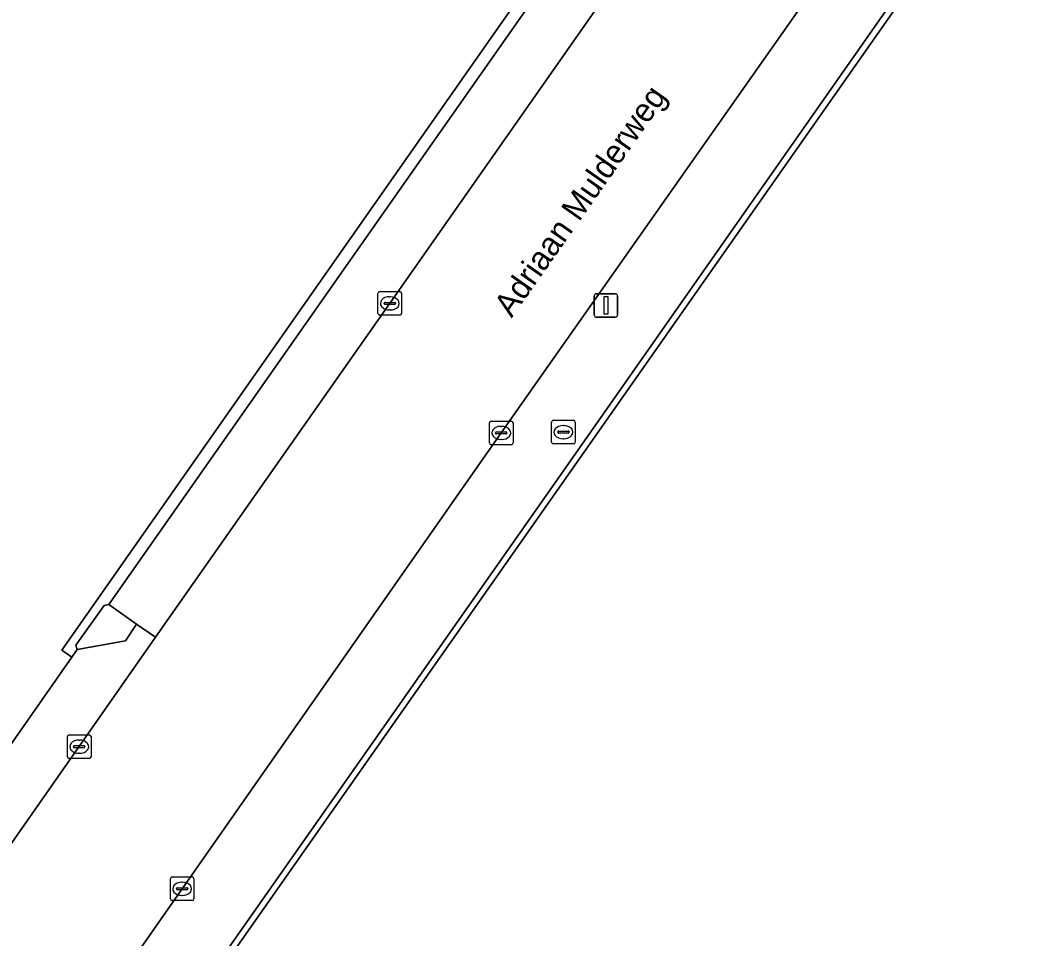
# Model space of a CAD drawing. Extents: x 155018 to 156648, y 383979 to 385733.
# Drawn here: x 155613.96 to 155656.36, y 384791.48 to 384830.45 of the extents above; entities that cross this region are included whole.
import ezdxf

# ---------------------------------------------------------------- set-up
doc = ezdxf.new("R2010")
doc.units = 0
for name, color, linetype in [('IMGEO_Brandkraan', 7, 'Continuous'), ('IMGEO_Erf', 7, 'Continuous'), ('IMGEO_Groenvoorziening', 7, 'Continuous'), ('IMGEO_Hek', 7, 'Continuous'), ('IMGEO_Kolk', 7, 'Continuous'), ('IMGEO_Lichtmast', 7, 'Continuous'), ('IMGEO_Openbare_ruimte_label', 7, 'Continuous'), ('IMGEO_Parkeervlak_open', 7, 'Continuous'), ('IMGEO_Rijbaan_lokaal_gesloten', 7, 'Continuous'), ('IMGEO_Verkeerseiland_open', 7, 'Continuous'), ('IMGEO_Voetpad_open', 7, 'Continuous')]:
    doc.layers.add(name, color=color, linetype=linetype)

msp = doc.modelspace()

# ---------------------------------------------------------------- linework, layer by layer
at = {"layer": 'IMGEO_Brandkraan'}
for p, q in [((155636.527, 384812.529), (155636.527, 384813.381)), ((155636.602, 384813.455), (155637.454, 384813.455)), ((155637.015, 384813.235), (155637.04, 384813.235)), ((155637.528, 384813.381), (155637.528, 384812.529)), ((155636.786, 384812.949), (155636.786, 384812.961)), ((155637.224, 384812.912), (155636.826, 384812.912)), ((155636.829, 384812.998), (155637.227, 384812.998)), ((155637.27, 384812.961), (155637.27, 384812.949)), ((155637.454, 384812.455), (155636.602, 384812.455)), ((155637.038, 384812.675), (155637.013, 384812.675))]:
    msp.add_line(p, q, dxfattribs=at)
for points in [[(155636.527, 384812.529), (155636.527, 384813.381)], [(155636.602, 384813.455), (155637.454, 384813.455)], [(155637.528, 384813.381), (155637.528, 384812.529)], [(155637.454, 384812.455), (155636.602, 384812.455)]]:
    msp.add_lwpolyline(points, dxfattribs=at)
for centre, radius, start, end in [((155636.604, 384813.379), 0.0765, 91.552, 178.448), ((155636.604, 384813.379), 0.0765, 91.552, 178.448), ((155637.452, 384813.379), 0.0765, 1.552, 88.448), ((155637.452, 384813.379), 0.0765, 1.552, 88.448), ((155636.826, 384812.958), 0.0403, 85.8775, 175.7526), ((155636.823, 384812.948), 0.0366, 178.938, 274.7102), ((155637.227, 384812.955), 0.043, 264.8664, 352.4533), ((155637.231, 384812.96), 0.0386, 1.7309, 96.639), ((155636.604, 384812.531), 0.0765, 181.552, 268.448), ((155636.604, 384812.531), 0.0765, 181.552, 268.448), ((155637.452, 384812.531), 0.0765, 271.552, 358.448), ((155637.452, 384812.531), 0.0765, 271.552, 358.448)]:
    msp.add_arc(centre, radius, start, end, dxfattribs=at)
for centre, major_axis, ratio, start_param, end_param in [((155637.014, 384812.955), (-0.387, 0.002), 0.722429, 4.712389, 7.853982), ((155637.039, 384812.955), (-0.39, 0.002), 0.717154, 1.570796, 4.712389)]:
    msp.add_ellipse(centre, major_axis=major_axis, ratio=ratio, start_param=start_param, end_param=end_param, dxfattribs=at)
at = {"layer": 'IMGEO_Erf'}
for points in [[(155730.975, 385018.536), (155724.402, 385000), (155719.139, 384985.171), (155718.598, 384983.687), (155716.009, 384976.585), (155715.7, 384975.738), (155702.844, 384939.771), (155702.172, 384937.868), (155696.786, 384922.628), (155696.12, 384920.743), (155684.958, 384889.381), (155684.425, 384889.57), (155682.806, 384885.06), (155682.424, 384883.902), (155681.972, 384882.563), (155681.138, 384880.234), (155681.15, 384879.519), (155676.547, 384866.454), (155676.35, 384866.575), (155669.497, 384856.797), (155669.212, 384856.331), (155667.198, 384853.508), (155667.02, 384853.625), (155588.106, 384741.158)], [(155553.633, 384715.232), (155553.739, 384715.172), (155553.747, 384715.183), (155566.056, 384732.66), (155578.198, 384750), (155612.129, 384798.458), (155612.508, 384798.198), (155616.168, 384803.406), (155615.737, 384803.696), (155649.459, 384851.832), (155649.247, 384851.98)]]:
    msp.add_lwpolyline(points, dxfattribs=at)
at = {"layer": 'IMGEO_Groenvoorziening'}
msp.add_lwpolyline([(155667.02, 384853.625), (155667.198, 384853.508), (155669.212, 384856.331), (155669.497, 384856.797), (155668.817, 384856.954), (155660.389, 384844.659), (155636.862, 384811.074), (155608.808, 384771.107), (155594.019, 384750), (155586.655, 384739.49), (155582.342, 384733.152), (155582.316, 384732.95), (155582.416, 384732.885), (155582.631, 384733.19), (155586.789, 384739.087), (155588.217, 384741.112), (155588.106, 384741.158)], close=True, dxfattribs=at)
at = {"layer": 'IMGEO_Hek'}
msp.add_lwpolyline([(155586.789, 384739.087), (155588.217, 384741.112), (155588.106, 384741.158), (155667.02, 384853.625), (155667.198, 384853.508), (155669.212, 384856.331)], dxfattribs=at)
at = {"layer": 'IMGEO_Kolk'}
for p, q in [((155629.158, 384817.995), (155629.158, 384818.847)), ((155629.233, 384818.921), (155630.085, 384818.921)), ((155629.646, 384818.701), (155629.671, 384818.701)), ((155630.159, 384818.847), (155630.159, 384817.995)), ((155629.417, 384818.415), (155629.417, 384818.427)), ((155629.855, 384818.378), (155629.457, 384818.378)), ((155629.46, 384818.464), (155629.858, 384818.464)), ((155629.901, 384818.427), (155629.901, 384818.415)), ((155630.085, 384817.921), (155629.233, 384817.921)), ((155629.669, 384818.141), (155629.644, 384818.141)), ((155633.888, 384812.493), (155633.888, 384813.345)), ((155633.963, 384813.419), (155634.815, 384813.419)), ((155634.376, 384813.199), (155634.401, 384813.199)), ((155634.889, 384813.345), (155634.889, 384812.493)), ((155634.147, 384812.913), (155634.147, 384812.925)), ((155634.585, 384812.876), (155634.187, 384812.876)), ((155634.19, 384812.962), (155634.588, 384812.962)), ((155634.631, 384812.925), (155634.631, 384812.913)), ((155634.815, 384812.419), (155633.963, 384812.419)), ((155634.399, 384812.639), (155634.374, 384812.639)), ((155615.977, 384799.176), (155615.977, 384800.028)), ((155616.052, 384800.102), (155616.904, 384800.102)), ((155616.978, 384800.028), (155616.978, 384799.176)), ((155616.236, 384799.596), (155616.236, 384799.608)), ((155616.279, 384799.645), (155616.677, 384799.645)), ((155616.465, 384799.882), (155616.49, 384799.882)), ((155616.72, 384799.608), (155616.72, 384799.596)), ((155616.674, 384799.559), (155616.276, 384799.559)), ((155616.488, 384799.322), (155616.463, 384799.322)), ((155616.904, 384799.102), (155616.052, 384799.102)), ((155620.42, 384794.069), (155621.272, 384794.069)), ((155620.345, 384793.143), (155620.345, 384793.995)), ((155620.833, 384793.849), (155620.858, 384793.849)), ((155621.346, 384793.995), (155621.346, 384793.143)), ((155620.604, 384793.563), (155620.604, 384793.575)), ((155621.042, 384793.526), (155620.644, 384793.526)), ((155620.647, 384793.612), (155621.045, 384793.612)), ((155620.856, 384793.289), (155620.831, 384793.289)), ((155621.088, 384793.575), (155621.088, 384793.563)), ((155621.272, 384793.069), (155620.42, 384793.069))]:
    msp.add_line(p, q, dxfattribs=at)
for points in [[(155629.158, 384817.995), (155629.158, 384818.847)], [(155629.233, 384818.921), (155630.085, 384818.921)], [(155630.159, 384818.847), (155630.159, 384817.995)], [(155630.085, 384817.921), (155629.233, 384817.921)], [(155633.888, 384812.493), (155633.888, 384813.345)], [(155633.963, 384813.419), (155634.815, 384813.419)], [(155634.889, 384813.345), (155634.889, 384812.493)], [(155634.815, 384812.419), (155633.963, 384812.419)], [(155615.977, 384799.176), (155615.977, 384800.028)], [(155616.052, 384800.102), (155616.904, 384800.102)], [(155616.978, 384800.028), (155616.978, 384799.176)], [(155616.904, 384799.102), (155616.052, 384799.102)], [(155620.42, 384794.069), (155621.272, 384794.069)], [(155620.345, 384793.143), (155620.345, 384793.995)], [(155621.346, 384793.995), (155621.346, 384793.143)], [(155621.272, 384793.069), (155620.42, 384793.069)]]:
    msp.add_lwpolyline(points, dxfattribs=at)
for centre, radius, start, end in [((155629.235, 384818.845), 0.0765, 91.552, 178.448), ((155629.235, 384818.845), 0.0765, 91.552, 178.448), ((155630.083, 384818.845), 0.0765, 1.552, 88.448), ((155630.083, 384818.845), 0.0765, 1.552, 88.448), ((155629.457, 384818.424), 0.0403, 85.8775, 175.7526), ((155629.454, 384818.414), 0.0366, 178.938, 274.7102), ((155629.858, 384818.421), 0.043, 264.8664, 352.4533), ((155629.862, 384818.426), 0.0386, 1.7309, 96.639), ((155629.235, 384817.997), 0.0765, 181.552, 268.448), ((155629.235, 384817.997), 0.0765, 181.552, 268.448), ((155630.083, 384817.997), 0.0765, 271.552, 358.448), ((155630.083, 384817.997), 0.0765, 271.552, 358.448), ((155633.965, 384813.343), 0.0765, 91.552, 178.448), ((155633.965, 384813.343), 0.0765, 91.552, 178.448), ((155634.813, 384813.343), 0.0765, 1.552, 88.448), ((155634.813, 384813.343), 0.0765, 1.552, 88.448), ((155634.187, 384812.922), 0.0403, 85.8775, 175.7526), ((155634.184, 384812.912), 0.0366, 178.938, 274.7102), ((155634.588, 384812.919), 0.043, 264.8664, 352.4533), ((155634.592, 384812.924), 0.0386, 1.7309, 96.639), ((155633.965, 384812.495), 0.0765, 181.552, 268.448), ((155633.965, 384812.495), 0.0765, 181.552, 268.448), ((155634.813, 384812.495), 0.0765, 271.552, 358.448), ((155634.813, 384812.495), 0.0765, 271.552, 358.448), ((155616.054, 384800.026), 0.0765, 91.552, 178.448), ((155616.054, 384800.026), 0.0765, 91.552, 178.448), ((155616.902, 384800.026), 0.0765, 1.552, 88.448), ((155616.902, 384800.026), 0.0765, 1.552, 88.448), ((155616.276, 384799.605), 0.0403, 85.8775, 175.7526), ((155616.273, 384799.595), 0.0366, 178.938, 274.7102), ((155616.677, 384799.602), 0.043, 264.8664, 352.4533), ((155616.681, 384799.607), 0.0386, 1.7309, 96.639), ((155616.054, 384799.178), 0.0765, 181.552, 268.448), ((155616.054, 384799.178), 0.0765, 181.552, 268.448), ((155616.902, 384799.178), 0.0765, 271.552, 358.448), ((155616.902, 384799.178), 0.0765, 271.552, 358.448), ((155620.422, 384793.993), 0.0765, 91.552, 178.448), ((155620.422, 384793.993), 0.0765, 91.552, 178.448), ((155621.27, 384793.993), 0.0765, 1.552, 88.448), ((155621.27, 384793.993), 0.0765, 1.552, 88.448), ((155620.644, 384793.572), 0.0403, 85.8775, 175.7526), ((155620.641, 384793.562), 0.0366, 178.938, 274.7102), ((155621.045, 384793.569), 0.043, 264.8664, 352.4533), ((155621.049, 384793.574), 0.0386, 1.7309, 96.639), ((155620.422, 384793.145), 0.0765, 181.552, 268.448), ((155620.422, 384793.145), 0.0765, 181.552, 268.448), ((155621.27, 384793.145), 0.0765, 271.552, 358.448), ((155621.27, 384793.145), 0.0765, 271.552, 358.448)]:
    msp.add_arc(centre, radius, start, end, dxfattribs=at)
for centre, major_axis, ratio, start_param, end_param in [((155629.645, 384818.421), (-0.387, 0.002), 0.722429, 4.712389, 7.853982), ((155629.67, 384818.421), (-0.39, 0.002), 0.717154, 1.570796, 4.712389), ((155634.375, 384812.919), (-0.387, 0.002), 0.722429, 4.712389, 7.853982), ((155634.4, 384812.919), (-0.39, 0.002), 0.717154, 1.570796, 4.712389), ((155616.464, 384799.602), (-0.387, 0.002), 0.722429, 4.712389, 7.853982), ((155616.489, 384799.602), (-0.39, 0.002), 0.717154, 1.570796, 4.712389), ((155620.832, 384793.569), (-0.387, 0.002), 0.722429, 4.712389, 7.853982), ((155620.857, 384793.569), (-0.39, 0.002), 0.717154, 1.570796, 4.712389)]:
    msp.add_ellipse(centre, major_axis=major_axis, ratio=ratio, start_param=start_param, end_param=end_param, dxfattribs=at)
at = {"layer": 'IMGEO_Lichtmast'}
for p, q in [((155638.336, 384817.931), (155638.336, 384818.731)), ((155638.336, 384818.731), (155638.336, 384817.931)), ((155638.436, 384818.831), (155639.226, 384818.831)), ((155639.226, 384818.831), (155638.436, 384818.831)), ((155639.326, 384818.731), (155639.326, 384817.931)), ((155639.326, 384817.931), (155639.326, 384818.731)), ((155639.226, 384817.831), (155638.436, 384817.831)), ((155638.436, 384817.831), (155639.226, 384817.831))]:
    msp.add_line(p, q, dxfattribs=at)
msp.add_lwpolyline([(155638.756, 384818.706), (155638.906, 384818.706), (155638.906, 384817.956), (155638.756, 384817.956), (155638.756, 384818.706)], dxfattribs=at)
for centre, start, end in [((155638.436, 384818.731), 90, 180), ((155638.436, 384818.731), 90, 180), ((155639.226, 384818.731), 0, 90), ((155639.226, 384818.731), 360, 90), ((155638.436, 384817.931), 180, 270), ((155638.436, 384817.931), 180, 270), ((155639.226, 384817.931), 270, 0), ((155639.226, 384817.931), 270, 0)]:
    msp.add_arc(centre, 0.1, start, end, dxfattribs=at)
at = {"layer": 'IMGEO_Parkeervlak_open'}
msp.add_lwpolyline([(155649.878, 384851.473), (155627.894, 384820.122), (155617.739, 384805.63), (155618.908, 384804.799), (155619.716, 384804.252), (155629.679, 384818.438), (155652.394, 384850.88)], dxfattribs=at)
at = {"layer": 'IMGEO_Rijbaan_lokaal_gesloten'}
for points in [[(155557.839, 384704.064), (155557.967, 384704.242), (155558.339, 384703.973), (155565.165, 384713.55), (155573.586, 384725.999), (155578.096, 384732.463), (155583.356, 384740.042), (155586.289, 384744.214), (155590.343, 384750), (155608.173, 384775.45), (155620.847, 384793.568), (155634.39, 384812.919), (155647.778, 384831.987), (155658, 384846.57), (155663.285, 384854.104), (155665.547, 384857.446), (155665.874, 384857.967)], [(155652.394, 384850.88), (155629.679, 384818.438), (155619.716, 384804.252), (155613.015, 384794.672), (155602.107, 384779.088), (155598.478, 384773.909), (155581.725, 384750), (155573.395, 384738.09), (155569.504, 384732.554), (155555.663, 384712.8)]]:
    msp.add_lwpolyline(points, dxfattribs=at)
at = {"layer": 'IMGEO_Verkeerseiland_open'}
msp.add_lwpolyline([(155616.394, 384803.727), (155618.447, 384804.097), (155618.908, 384804.799), (155617.739, 384805.63), (155617.539, 384805.599), (155616.33, 384803.906)], close=True, dxfattribs=at)
at = {"layer": 'IMGEO_Voetpad_open'}
for points in [[(155586.655, 384739.49), (155594.019, 384750), (155608.808, 384771.107), (155636.862, 384811.074), (155660.389, 384844.659), (155668.817, 384856.954), (155665.874, 384857.967), (155665.547, 384857.446), (155663.285, 384854.104), (155658, 384846.57), (155647.778, 384831.987), (155634.39, 384812.919), (155620.847, 384793.568), (155608.173, 384775.45), (155590.343, 384750), (155586.289, 384744.214)], [(155616.394, 384803.727), (155616.168, 384803.406), (155612.508, 384798.198), (155612.346, 384797.968), (155612.719, 384795.936), (155612.249, 384795.277), (155613.015, 384794.672), (155619.716, 384804.252), (155618.908, 384804.799), (155618.447, 384804.097)]]:
    msp.add_lwpolyline(points, close=True, dxfattribs=at)
msp.add_lwpolyline([(155649.247, 384851.98), (155649.459, 384851.832), (155615.737, 384803.696), (155616.168, 384803.406), (155616.394, 384803.727), (155616.33, 384803.906), (155617.539, 384805.599), (155617.739, 384805.63), (155627.894, 384820.122), (155649.878, 384851.473)], dxfattribs=at)

# ---------------------------------------------------------------- texts
at = {"layer": 'IMGEO_Openbare_ruimte_label'}
msp.add_text('Adriaan Mulderweg', height=1, rotation=54.9751, dxfattribs=at).set_placement((155634.83, 384817.775))

doc.saveas('drawing.dxf')
